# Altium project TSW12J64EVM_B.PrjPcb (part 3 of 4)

## Sheet TSW12J64EVM_B_8_Power.SchDoc
size 431 x 279 mm; Date: Not shown in title block; ApprovedBy: Not shown in title block; CheckedBy: Not shown in title block; Author: Not shown in title block; CompanyName: Not shown in title block; Engineer: Not shown in title block; Organization: Not shown in title block; Address1: Not shown in title block; Address2: Not shown in title block; Address3: Not shown in title block; Address4: Not shown in title block; DocumentNumber: 8; Revision: Use project parameter SCH_Rev; SheetNumber: 8; SheetTotal: 11; PageSetup: Record=PageOptions¦CenterHorizontal=True¦CenterVertical=True¦PrintScale=0.64¦XCorrection=1.00¦YCorrection=1.00¦PrintKind=0¦BorderSize=5000000¦LeftOffset=0¦BottomOffset=0¦Orientation=2¦PaperLength=1000¦PaperWidth=1000¦Scale=100¦PaperSource=15¦PrintQuality=600¦MediaType=1¦DitherType=10¦PaperKind=11x17¦PrintScaleMode=1
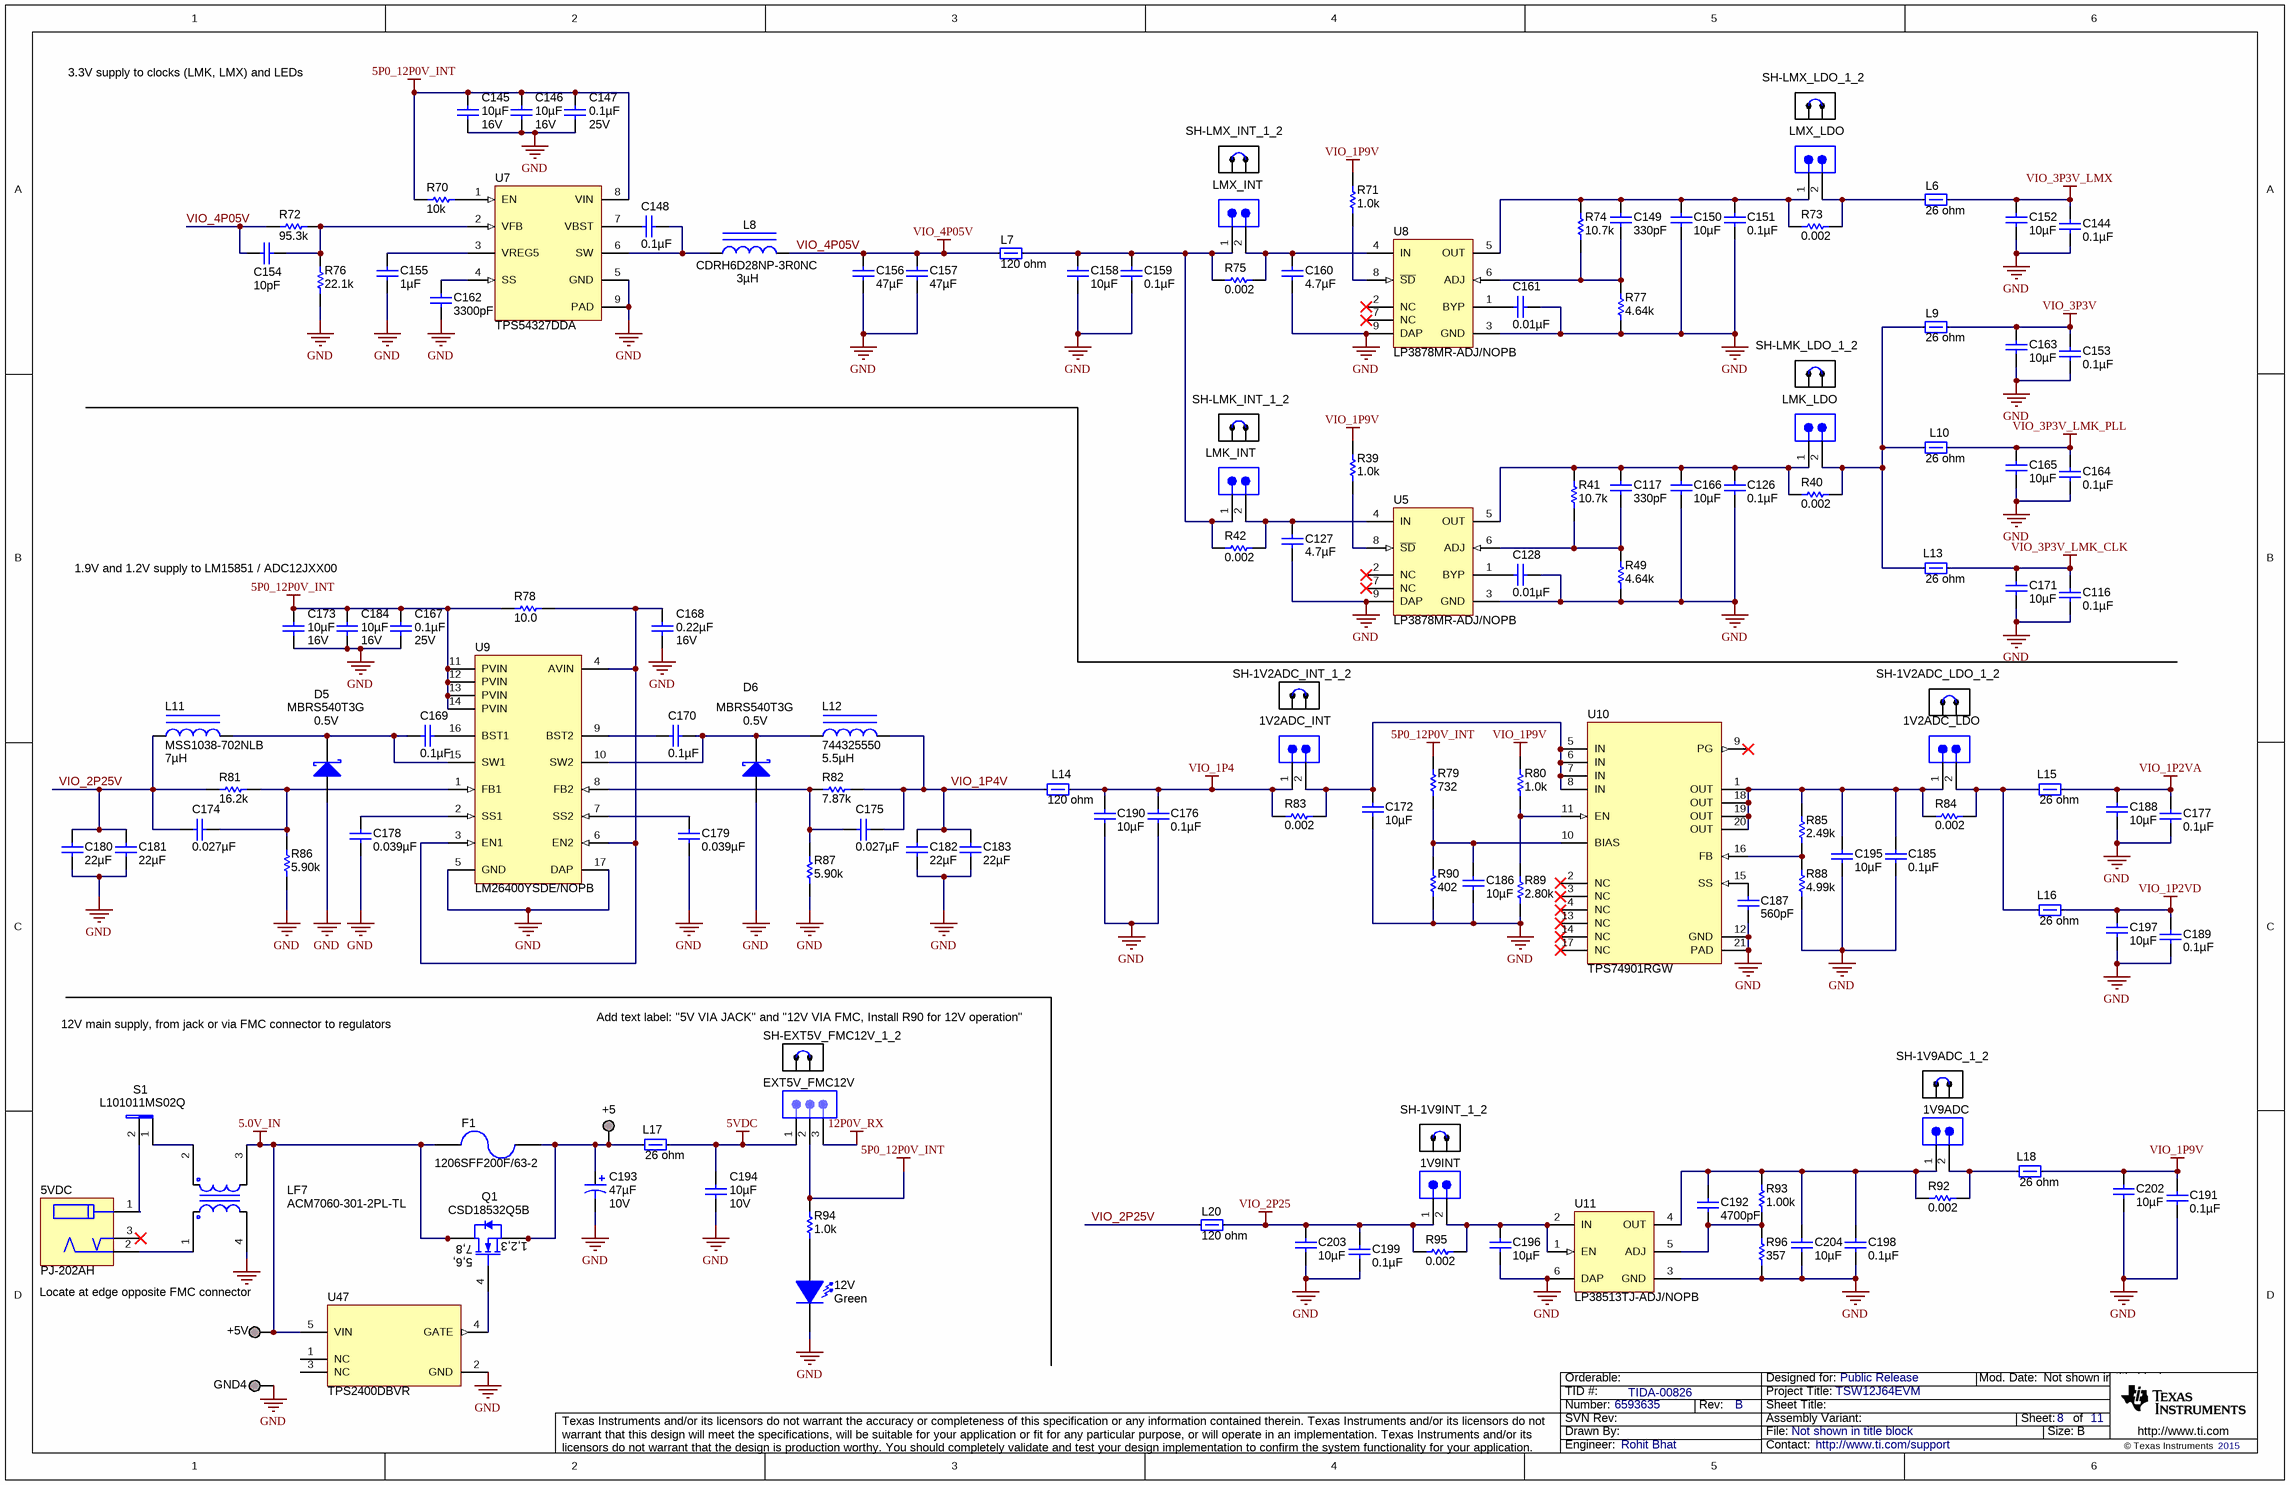
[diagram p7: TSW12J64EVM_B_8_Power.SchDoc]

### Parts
1V2ADC_INT  TSW-102-07-G-S  [TSW-102-07-G-S]  (value not drawn)
1V2ADC_LDO  TSW-102-07-G-S  [TSW-102-07-G-S]  (value not drawn)
1V9ADC  TSW-102-07-G-S  [TSW-102-07-G-S]  (value not drawn)
1V9INT  TSW-102-07-G-S  [TSW-102-07-G-S]  (value not drawn)
5VDC  PJ-202AH  [CONN_CUI-PJ-202AH]
12V  value Green  [LED_LTST-C190]  (hidden comment: LTST-C190GKT)
+5  TESTPOINT  [TP_VIA_060RND040]  (value not drawn)  (no BOM)
+5V  TESTPOINT  [TP_VIA_060RND040]  (value not drawn)  (no BOM)
C116  ValueDisplayed: 0.1µF  [0603L]  (hidden comment: 06033C104JAT2A)
C117  ValueDisplayed: 330pF  [0603L]  (hidden comment: 06035A331JAT2A)
C126  ValueDisplayed: 0.1µF  [0603L]  (hidden comment: 06033C104JAT2A)
C127  ValueDisplayed: 4.7µF  [0603L]  (hidden comment: C0603C475K8PACTU)
C128  ValueDisplayed: 0.01µF  [0603L]  (hidden comment: 06031C103MAT2A)
C144  ValueDisplayed: 0.1µF  [0603L]  (hidden comment: 06033C104JAT2A)
C145  ValueDisplayed: 10µF  Value2: 16V  [0805L]  (hidden comment: EMK212BJ106KG-T)
C146  ValueDisplayed: 10µF  Value2: 16V  [0805L]  (hidden comment: EMK212BJ106KG-T)
C147  ValueDisplayed: 0.1µF  Value2: 25V  [0603L]  (hidden comment: 06033C104JAT2A)
C148  ValueDisplayed: 0.1µF  [0603L]  (hidden comment: 06033C104JAT2A)
C149  ValueDisplayed: 330pF  [0603L]  (hidden comment: 06035A331JAT2A)
C150  ValueDisplayed: 10µF  [0603L]  (hidden comment: C1608X5R1A106M)
C151  ValueDisplayed: 0.1µF  [0603L]  (hidden comment: 06033C104JAT2A)
C152  ValueDisplayed: 10µF  [0603L]  (hidden comment: C1608X5R1A106M)
C153  ValueDisplayed: 0.1µF  [0603L]  (hidden comment: 06033C104JAT2A)
C154  ValueDisplayed: 10pF  [0603L]  (hidden comment: 06035A100JAT2A)
C155  ValueDisplayed: 1µF  [0603L]  (hidden comment: C1608X5R1C105K)
C156  ValueDisplayed: 47µF  [1206L]  (hidden comment: GRM31CR60J476ME19L)
C157  ValueDisplayed: 47µF  [1206L]  (hidden comment: GRM31CR60J476ME19L)
C158  ValueDisplayed: 10µF  [0603L]  (hidden comment: C1608X5R1A106M)
C159  ValueDisplayed: 0.1µF  [0603L]  (hidden comment: 06033C104JAT2A)
C160  ValueDisplayed: 4.7µF  [0603L]  (hidden comment: C0603C475K8PACTU)
C161  ValueDisplayed: 0.01µF  [0603L]  (hidden comment: 06031C103MAT2A)
C162  ValueDisplayed: 3300pF  [0603L]  (hidden comment: GRM188R71E332KA01D)
C163  ValueDisplayed: 10µF  [0603L]  (hidden comment: C1608X5R1A106M)
C164  ValueDisplayed: 0.1µF  [0603L]  (hidden comment: 06033C104JAT2A)
C165  ValueDisplayed: 10µF  [0603L]  (hidden comment: C1608X5R1A106M)
C166  ValueDisplayed: 10µF  [0603L]  (hidden comment: C1608X5R1A106M)
C167  ValueDisplayed: 0.1µF  Value2: 25V  [0603L]  (hidden comment: 06033C104JAT2A)
C168  ValueDisplayed: 0.22µF  Value2: 16V  [0603L]  (hidden comment: C1608X7R1C224K)
C169  ValueDisplayed: 0.1µF  [0402L]  (hidden comment: GRM155R60J104KA01D)
C170  ValueDisplayed: 0.1µF  [0402L]  (hidden comment: GRM155R60J104KA01D)
C171  ValueDisplayed: 10µF  [0603L]  (hidden comment: C1608X5R1A106M)
C172  ValueDisplayed: 10µF  [0603L]  (hidden comment: C1608X5R1A106M)
C173  ValueDisplayed: 10µF  Value2: 16V  [0805L]  (hidden comment: EMK212BJ106KG-T)
C174  ValueDisplayed: 0.027µF  [0603L]  (hidden comment: GRM188R71C273KA01D)
C175  ValueDisplayed: 0.027µF  [0603L]  (hidden comment: GRM188R71C273KA01D)
C176  ValueDisplayed: 0.1µF  [0603L]  (hidden comment: 06033C104JAT2A)
C177  ValueDisplayed: 0.1µF  [0603L]  (hidden comment: 06033C104JAT2A)
C178  ValueDisplayed: 0.039µF  [0603L]  (hidden comment: 06033C393KAT2A)
C179  ValueDisplayed: 0.039µF  [0603L]  (hidden comment: 06033C393KAT2A)
C180  ValueDisplayed: 22µF  [1206L]  (hidden comment: GRM31CR61A226ME19L)
C181  ValueDisplayed: 22µF  [1206L]  (hidden comment: GRM31CR61A226ME19L)
C182  ValueDisplayed: 22µF  [1206L]  (hidden comment: GRM31CR61A226ME19L)
C183  ValueDisplayed: 22µF  [1206L]  (hidden comment: GRM31CR61A226ME19L)
C184  ValueDisplayed: 10µF  Value2: 16V  [0805L]  (hidden comment: EMK212BJ106KG-T)
C185  ValueDisplayed: 0.1µF  [0603L]  (hidden comment: 06033C104JAT2A)
C186  ValueDisplayed: 10µF  [0603L]  (hidden comment: C1608X5R1A106M)
C187  ValueDisplayed: 560pF  [0603L]  (hidden comment: 06035A561JAT2A)
C188  ValueDisplayed: 10µF  [0603L]  (hidden comment: C1608X5R1A106M)
C189  ValueDisplayed: 0.1µF  [0603L]  (hidden comment: 06033C104JAT2A)
C190  ValueDisplayed: 10µF  [0603L]  (hidden comment: C1608X5R1A106M)
C191  ValueDisplayed: 0.1µF  [0603L]  (hidden comment: 06033C104JAT2A)
C192  ValueDisplayed: 4700pF  [0603L]  (hidden comment: GRM188R71C472KA01D)
C193  ValueDisplayed: 47µF  Value2: 10V  [3528-21]  (hidden comment: TPSB476K010R0250)
C194  ValueDisplayed: 10µF  Value2: 10V  [0603L]  (hidden comment: C1608X5R1A106M)
C195  ValueDisplayed: 10µF  [0603L]  (hidden comment: C1608X5R1A106M)
C196  ValueDisplayed: 10µF  [0603L]  (hidden comment: C1608X5R1A106M)
C197  ValueDisplayed: 10µF  [0603L]  (hidden comment: C1608X5R1A106M)
C198  ValueDisplayed: 0.1µF  [0603L]  (hidden comment: 06033C104JAT2A)
C199  ValueDisplayed: 0.1µF  [0603L]  (hidden comment: 06033C104JAT2A)
C202  ValueDisplayed: 10µF  [0603L]  (hidden comment: C1608X5R1A106M)
C203  ValueDisplayed: 10µF  [0603L]  (hidden comment: C1608X5R1A106M)
C204  ValueDisplayed: 10µF  [0603L]  (hidden comment: C1608X5R1A106M)
D5  MBRS540T3G  value 0.5V  [SMC]
D6  MBRS540T3G  value 0.5V  [SMC]
EXT5V_FMC12V  PBC03SAAN  [PBC03SAAN]  (value not drawn)
F1  1206SFF200F/63-2  [1206]
GND4  TESTPOINT  [TP_VIA_060RND040]  (value not drawn)  (no BOM)
L6  value 26 ohm  [0603]  (hidden comment: BLM18SG260TN1D)
L7  value 120 ohm  [0603]  (hidden comment: BLM18SG121TN1D)
L8  CDRH6D28NP-3R0NC  ValueDisplayed: 3µH  [CDRH6D28]
L9  value 26 ohm  [0603]  (hidden comment: BLM18SG260TN1D)
L10  value 26 ohm  [0603]  (hidden comment: BLM18SG260TN1D)
L11  MSS1038-702NLB  ValueDisplayed: 7µH  [MSS1038]
L12  744325550  ValueDisplayed: 5.5µH  [WE-HC6]
L13  value 26 ohm  [0603]  (hidden comment: BLM18SG260TN1D)
L14  value 120 ohm  [0603]  (hidden comment: BLM18SG121TN1D)
L15  value 26 ohm  [0603]  (hidden comment: BLM18SG260TN1D)
L16  value 26 ohm  [0603]  (hidden comment: BLM18SG260TN1D)
L17  value 26 ohm  [0603]  (hidden comment: BLM18SG260TN1D)
L18  value 26 ohm  [0603]  (hidden comment: BLM18SG260TN1D)
L20  value 120 ohm  [0603]  (hidden comment: BLM18SG121TN1D)
LF7  ACM7060-301-2PL-TL  [IND_TDK_ACM7060]
LMK_INT  TSW-102-07-G-S  [TSW-102-07-G-S]  (value not drawn)
LMK_LDO  TSW-102-07-G-S  [TSW-102-07-G-S]  (value not drawn)
LMX_INT  TSW-102-07-G-S  [TSW-102-07-G-S]  (value not drawn)
LMX_LDO  TSW-102-07-G-S  [TSW-102-07-G-S]  (value not drawn)
Q1  CSD18532Q5B  [TRANS_NexFET_Q5B]
R39  value 1.0k  [0603L]  (hidden comment: RC0603JR-071KL)
R40  value 0.002  [1206]  (hidden comment: CSNL1206FT2L00)
R41  value 10.7k  [0603L]  (hidden comment: CRCW060310K7FKEA)
R42  value 0.002  [1206]  (hidden comment: CSNL1206FT2L00)
R49  value 4.64k  [0603L]  (hidden comment: RC0603FR-074K64L)
R70  value 10k  [0603L]  (hidden comment: RC0603JR-0710KL)
R71  value 1.0k  [0603L]  (hidden comment: RC0603JR-071KL)
R72  ValueDisplayed: 95.3k  [0603L]  (hidden comment: RC0603FR-0795K3L)
R73  value 0.002  [1206]  (hidden comment: CSNL1206FT2L00)
R74  value 10.7k  [0603L]  (hidden comment: CRCW060310K7FKEA)
R75  value 0.002  [1206]  (hidden comment: CSNL1206FT2L00)
R76  value 22.1k  [0603L]  (hidden comment: CRCW060322K1FKEA)
R77  value 4.64k  [0603L]  (hidden comment: RC0603FR-074K64L)
R78  value 10.0  [0603L]  (hidden comment: RC0603FR-0710RL)
R79  value 732  [0603L]  (hidden comment: CRCW0603732RFKEA)
R80  value 1.0k  [0603L]  (hidden comment: RC0603JR-071KL)
R81  value 16.2k  [0603L]  (hidden comment: CRCW060316K2FKEA)
R82  value 7.87k  [0603L]  (hidden comment: CRCW06037K87FKEA)
R83  value 0.002  [1206]  (hidden comment: CSNL1206FT2L00)
R84  value 0.002  [1206]  (hidden comment: CSNL1206FT2L00)
R85  value 2.49k  [0603L]  (hidden comment: CRCW06032K49FKEA)
R86  value 5.90k  [0603L]  (hidden comment: CRCW06035K90FKEA)
R87  value 5.90k  [0603L]  (hidden comment: CRCW06035K90FKEA)
R88  value 4.99k  [0603L]  (hidden comment: CRCW06034K99FKEA)
R89  value 2.80k  [0603L]  (hidden comment: CRCW06032K80FKEA)
R90  value 402  [0603L]  (hidden comment: RC0603FR-07402RL)
R92  value 0.002  [1206]  (hidden comment: CSNL1206FT2L00)
R93  value 1.00k  [0603L]  (hidden comment: RC0603FR-071KL)
R94  value 1.0k  [1206L]  (hidden comment: CRCW12061K00JNEA)
R95  value 0.002  [1206]  (hidden comment: CSNL1206FT2L00)
R96  value 357  [0603L]  (hidden comment: RC0603FR-07357RL)
S1  L101011MS02Q  [SW_ L101011MS02Q]
SH-1V2ADC_INT_1_2  SNT-100-BK-G  [SNT-100-BK-G]  (value not drawn)
SH-1V2ADC_LDO_1_2  SNT-100-BK-G  [SNT-100-BK-G]  (value not drawn)
SH-1V9ADC_1_2  SNT-100-BK-G  [SNT-100-BK-G]  (value not drawn)
SH-1V9INT_1_2  SNT-100-BK-G  [SNT-100-BK-G]  (value not drawn)
SH-EXT5V_FMC12V_1_2  SNT-100-BK-G  [SNT-100-BK-G]  (value not drawn)
SH-LMK_INT_1_2  SNT-100-BK-G  [SNT-100-BK-G]  (value not drawn)
SH-LMK_LDO_1_2  SNT-100-BK-G  [SNT-100-BK-G]  (value not drawn)
SH-LMX_INT_1_2  SNT-100-BK-G  [SNT-100-BK-G]  (value not drawn)
SH-LMX_LDO_1_2  SNT-100-BK-G  [SNT-100-BK-G]  (value not drawn)
U5  LP3878MR-ADJ/NOPB  [MRA08A_N]
U7  TPS54327DDA  [DDA0008B_L]
U8  LP3878MR-ADJ/NOPB  [MRA08A_N]
U9  LM26400YSDE/NOPB  [SDA16A]
U10  TPS74901RGW  [RGW0020A]
U11  LP38513TJ-ADJ/NOPB  [TJ5A_N]
U47  TPS2400DBVR  [DBV0005A_N]

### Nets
5.0V_IN: +5V.1 F1.2 LF7.3 Q1.5(D) Q1.6(D) Q1.7(D) Q1.8(D) U47.5(VIN)
5P0_12P0V_INT: C145.1 C146.1 C147.1 C167.1 C173.1 C184.1 EXT5V_FMC12V.2 R70.1 R78.1 R79.2 R94.2 U7.8(VIN) U9.11(PVIN) U9.12(PVIN) U9.13(PVIN) U9.14(PVIN)
5VDC: C194.1 EXT5V_FMC12V.1 L17.2
12P0V_RX: EXT5V_FMC12V.3
GND: 12V.2(K) C116.2 C126.2 C127.2 C128.2 C144.2 C145.2 C146.2 C147.2 C150.2 C151.2 C152.2 C153.2 C155.2 C156.1 C157.1 C158.2 C159.2 C160.2 C161.2 C162.2 C163.2 C164.2 C165.2 C166.2 C167.2 C168.2 C171.2 C172.2 C173.2 C176.2 C177.2 C178.2 C179.2 C180.2 C181.2 C182.2 C183.2 C184.2 C185.2 C186.2 C187.2 C188.2 C189.2 C190.2 C191.2 C193.2(-) C194.2 C195.2 C196.2 C197.2 C198.2 C199.2 C202.2 C203.2 C204.2 D5.2(A) D6.2(A) GND4.1 LF7.4 R49.1 R76.1 R77.1 R86.1 R87.1 R88.1 R89.1 R90.1 R96.1 U5.3(GND) U5.9(DAP) U7.5(GND) U7.9(PAD) U8.3(GND) U8.9(DAP) U9.5(GND) U9.17(DAP) U10.12(GND) U10.21(PAD) U11.3(GND) U11.6(DAP) U47.2(GND)
VIO_1P2VA: C177.1 C188.1 L15.2
VIO_1P2VD: C189.1 C197.1 L16.2
VIO_1P4: 1V2ADC_INT.1 C176.1 C190.1 L14.2 R83.1
VIO_1P9V: C191.1 C202.1 L18.2 R39.1 R71.1 R80.1
VIO_2P25: 1V9INT.1 C199.1 C203.1 L20.2 R95.1
VIO_3P3V: C153.1 C163.1 L9.2
VIO_3P3V_LMK_CLK: C116.1 C171.1 L13.2
VIO_3P3V_LMK_PLL: C164.1 C165.1 L10.2
VIO_3P3V_LMX: C144.1 C152.1 L6.2
VIO_4P05V: C154.2 C156.2 C157.2 L7.1 L8.2 R72.1
VIO_1P4V: C175.1 C182.1 C183.1 L12.2 L14.1 R82.2
VIO_2P25V: C174.2 C180.1 C181.1 L11.1 L20.1 R81.1
Net1V2ADC_INT_2: 1V2ADC_INT.2 C172.1 R83.2 U10.5(IN) U10.6(IN) U10.7(IN) U10.8(IN)
Net1V2ADC_LDO_1: 1V2ADC_LDO.1 C185.1 C195.1 R84.1 R85.2 U10.1(OUT) U10.18(OUT) U10.19(OUT) U10.20(OUT)
Net1V2ADC_LDO_2: 1V2ADC_LDO.2 L15.1 L16.1 R84.2
Net1V9ADC_1: 1V9ADC.1 C192.1 C198.1 C204.1 R92.1 R93.2 U11.4(OUT)
Net1V9ADC_2: 1V9ADC.2 L18.1 R92.2
Net1V9INT_2: 1V9INT.2 C196.1 R95.2 U11.1(EN) U11.2(IN)
Net5VDC_1: 5VDC.1 S1.2
Net5VDC_2: 5VDC.2 LF7.1
Net12V_1: 12V.1(A) R94.1
Net+5_1: +5.1 C193.1(+) F1.1 L17.1 Q1.1(S) Q1.2(S) Q1.3(S)
NetC117_1: C117.1 C126.1 C166.1 LMK_LDO.1 R40.1 R41.2 U5.5(OUT)
NetC117_2: C117.2 R41.1 R49.2 U5.6(ADJ)
NetC127_1: C127.1 LMK_INT.2 R42.2 U5.4(IN)
NetC128_1: C128.1 U5.1(BYP)
NetC148_1: C148.1 L8.1 U7.6(SW)
NetC148_2: C148.2 U7.7(VBST)
NetC149_1: C149.1 C150.1 C151.1 LMX_LDO.1 R73.1 R74.2 U8.5(OUT)
NetC149_2: C149.2 R74.1 R77.2 U8.6(ADJ)
NetC154_1: C154.1 R72.2 R76.2 U7.2(VFB)
NetC155_1: C155.1 U7.3(VREG5)
NetC158_1: C158.1 C159.1 L7.2 LMK_INT.1 LMX_INT.1 R42.1 R75.1
NetC160_1: C160.1 LMX_INT.2 R75.2 U8.4(IN)
NetC161_1: C161.1 U8.1(BYP)
NetC162_1: C162.1 U7.4(SS)
NetC168_1: C168.1 R78.2 U9.3(EN1) U9.4(AVIN) U9.6(EN2)
NetC169_1: C169.1 U9.16(BST1)
NetC169_2: C169.2 D5.1(K) L11.2 U9.15(SW1)
NetC170_1: C170.1 D6.1(K) L12.1 U9.10(SW2)
NetC170_2: C170.2 U9.9(BST2)
NetC174_1: C174.1 R81.2 R86.2 U9.1(FB1)
NetC175_2: C175.2 R82.1 R87.2 U9.8(FB2)
NetC178_1: C178.1 U9.2(SS1)
NetC179_1: C179.1 U9.7(SS2)
NetC186_1: C186.1 R79.1 R90.2 U10.10(BIAS)
NetC187_1: C187.1 U10.15(SS)
NetC192_2: C192.2 R93.1 R96.2 U11.5(ADJ)
NetL6_1: L6.1 LMX_LDO.2 R73.2
NetL9_1: L9.1 L10.1 L13.1 LMK_LDO.2 R40.2
NetLF7_2: LF7.2 S1.1
NetQ1_4: Q1.4(G) U47.4(GATE)
NetR39_2: R39.2 U5.8(~{SD})
NetR70_2: R70.2 U7.1(EN)
NetR71_2: R71.2 U8.8(~{SD})
NetR80_2: R80.2 R89.2 U10.11(EN)
NetR85_1: R85.1 R88.2 U10.16(FB)

Not connected (* = marked no-connect by the designer): 5VDC 3*; U5 2(NC)* 7(NC)*; U8 2(NC)* 7(NC)*; U10 2(NC)* 3(NC)* 4(NC)* 9(PG)* 13(NC)* 14(NC)* 17(NC)*; U47 1(NC) 3(NC)

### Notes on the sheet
- 3.3V supply to clocks (LMK, LMX) and LEDs
- 1.9V and 1.2V supply to LM15851 / ADC12JXX00
- 12V main supply, from jack or via FMC connector to regulators
- (near SH-EXT5V_FMC12V_1_2) Add text label: "5V VIA JACK" and "12V VIA FMC, Install R90 for 12V operation"
- Locate at edge opposite FMC connector

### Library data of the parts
1V2ADC_INT 1V2ADC_LDO 1V9ADC 1V9INT LMK_INT LMK_LDO LMX_INT LMX_LDO = TSW-102-07-G-S: Header, TH, 100mil, 2x1, Gold plated, 230 mil above insulator; Manufacturer: Samtec, Inc.; U/M: EA
5VDC = PJ-202AH: Connector, DC Jack 2.1X5.5 mm, TH; Manufacturer: CUI Inc.; SymbolCreator: a0799628; U/M: EA
12V = LTST-C190GKT: LED, Green, SMD; Manufacturer: Lite-On; Vf_V: 2.1; Value2: 2.1V; Io_A: 0.02; Power_TotalModule: 0.1; Value1: 0.1W; U/M: EA
+5 +5V GND4 = TESTPOINT: TEST POINT.  No entry in BOM.
C116 C126 C144 C147 C148 C151 C153 C159 C164 C167 C176 C177 C185 C189 C191 C198 C199 = 06033C104JAT2A: CAP, CERM, 0.1uF, 25V, +/-5%, X7R, 0603; Manufacturer: AVX; Polarized: N; CompType: Capacitor; U/M: EA; Cap_F: 0.0000001; Tolerance_%: 5; ESR_Ohm: 0.05; Value1: 0.05 ohm; VDC_V: 25; TaMin_C: -55; TaMax_C: 125; Cap_Case: 0603
C117 C149 = 06035A331JAT2A: CAP, CERM, 330pF, 50V, +/-5%, C0G/NP0, 0603; Manufacturer: AVX; Polarized: N; CompType: Capacitor; U/M: EA; Cap_F: 0.00000000033; Tolerance_%: 5; ESR_Ohm: 0.071; Value1: 0.071 ohm; VDC_V: 50; TaMin_C: -55; TaMax_C: 125; Cap_Case: 0603
C127 C160 = C0603C475K8PACTU: CAP, CERM, 4.7uF, 10V, +/-10%, X5R, 0603; Manufacturer: Kemet; Polarized: N; CompType: Capacitor; U/M: EA; Cap_F: 0.0000047; Tolerance_%: 10; ESR_Ohm: 0.006; Value1: 0.006 ohm; IRMS_A: 7.24; TaMin_C: -55; TaMax_C: 85; Cap_Case: 0603
C128 C161 = 06031C103MAT2A: CAP, CERM, 0.01uF, 100V, +/-20%, X7R, 0603; Manufacturer: AVX; Polarized: N; CompType: Capacitor; U/M: EA; Cap_F: 0.00000001; Tolerance_%: 20; ESR_Ohm: 0.098; Value1: 0.098 ohm; VDC_V: 100; TaMin_C: -55; TaMax_C: 125; Cap_Case: 0603
C145 C146 C173 C184 = EMK212BJ106KG-T: CAP, CERM, 10uF, 16V, +/-10%, X5R, 0805; Manufacturer: Taiyo Yuden; Polarized: N; CompType: Capacitor; U/M: EA; Cap_F: 0.00001; Tolerance_%: 10; Value1: Unknown; VDC_V: 16; TaMin_C: -55; TaMax_C: 85; Cap_Case: 0805
C150 C152 C158 C163 C165 C166 C171 C172 C186 C188 C190 C194-C197 C202-C204 = C1608X5R1A106M: CAP, CERM, 10uF, 10V, +/-10%, C0G/NP0, 0603; Manufacturer: TDK; Polarized: N; CompType: Capacitor; U/M: EA; Cap_F: 0.00001; Tolerance_%: 10; ESR_Ohm: 0.0078; Value1: 0.0078 ohm; IRMS_A: 1.85; TaMin_C: -55; TaMax_C: 85; Cap_Case: 0603
C154 = 06035A100JAT2A: CAP, CERM, 10pF, 50V, +/-5%, C0G/NP0, 0603; Manufacturer: AVX; Polarized: N; CompType: Capacitor; U/M: EA; Cap_F: 0.00000000001; Tolerance_%: 5; ESR_Ohm: 0.403; Value1: 0.403 ohm; VDC_V: 50; TaMin_C: -55; TaMax_C: 125; Cap_Case: 0603
C155 = C1608X5R1C105K: CAP, CERM, 1uF, 16V, +/-10%, X5R, 0603; Manufacturer: TDK; Polarized: N; CompType: Capacitor; U/M: EA; Cap_F: 0.000001; Tolerance_%: 10; ESR_Ohm: 0.0057; Value1: 0.0057 ohm; VDC_V: 16; TaMin_C: -55; TaMax_C: 85; Cap_Case: 0603
C156 C157 = GRM31CR60J476ME19L: CAP, CERM, 47uF, 6.3V, +/-20%, X5R, 1206; Manufacturer: MuRata; Polarized: N; CompType: Capacitor; U/M: EA; Cap_F: 0.000047; Tolerance_%: 20; ESR_Ohm: 0.003; Value1: 0.003 ohm; VDC_V: 6.3; TaMin_C: -55; TaMax_C: 85; Cap_Case: 1206
C162 = GRM188R71E332KA01D: CAP, CERM, 3300pF, 25V, +/-10%, X7R, 0603; Manufacturer: MuRata; Polarized: N; CompType: Capacitor; U/M: EA; Cap_F: 0.0000000033; Tolerance_%: 10; VDC_V: 25; TaMin_C: -55; TaMax_C: 125; Cap_Case: 0603
C168 = C1608X7R1C224K: CAP, CERM, 0.22uF, 16V, +/-10%, X7R, 0603; Manufacturer: TDK; Polarized: N; CompType: Capacitor; U/M: EA; Cap_F: 0.00000022; Tolerance_%: 10; ESR_Ohm: 0.0125; Value1: 0.0125 ohm; VDC_V: 16; TaMin_C: -55; TaMax_C: 125; Cap_Case: 0603
C169 C170 = GRM155R60J104KA01D: CAP, CERM, 0.1uF, 6.3V, +/-10%, X5R, 0402; Manufacturer: MuRata; Polarized: N; CompType: Capacitor; U/M: EA; Cap_F: 0.0000001; Tolerance_%: 10; VDC_V: 6.3; TaMin_C: -55; TaMax_C: 85; Cap_Case: 0402
C174 C175 = GRM188R71C273KA01D: CAP, CERM, 0.027uF, 16V, +/-10%, X7R, 0603; Manufacturer: MuRata; Polarized: N; CompType: Capacitor; U/M: EA; Cap_F: 0.000000027; Tolerance_%: 10; VDC_V: 16; TaMin_C: -55; TaMax_C: 125; Cap_Case: 0603
C178 C179 = 06033C393KAT2A: CAP, CERM, 0.039uF, 25V, +/-10%, X7R, 0603; Manufacturer: AVX; Polarized: N; CompType: Capacitor; U/M: EA; Cap_F: 0.000000039; Tolerance_%: 10; ESR_Ohm: 0.056; Value1: 0.056 ohm; VDC_V: 25; TaMin_C: -55; TaMax_C: 125; Cap_Case: 0603
C180-C183 = GRM31CR61A226ME19L: CAP, CERM, 22uF, 10V, +/-20%, X5R, 1206; Manufacturer: MuRata; Polarized: N; CompType: Capacitor; U/M: EA; Cap_F: 0.000022; Tolerance_%: 20; ESR_Ohm: 0.007; Value1: 0.007 ohm; VDC_V: 10; TaMin_C: -55; TaMax_C: 85; Cap_Case: 1206
C187 = 06035A561JAT2A: CAP, CERM, 560pF, 50V, +/-5%, C0G/NP0, 0603; Manufacturer: AVX; Polarized: N; CompType: Capacitor; U/M: EA; Cap_F: 0.00000000056; Tolerance_%: 5; ESR_Ohm: 0.059; Value1: 0.059 ohm; VDC_V: 50; TaMin_C: -55; TaMax_C: 125; Cap_Case: 0603
C192 = GRM188R71C472KA01D: CAP, CERM, 4700pF, 16V, +/-10%, X7R, 0603; Manufacturer: MuRata; Polarized: N; CompType: Capacitor; U/M: EA; Cap_F: 0.0000000047; Tolerance_%: 10; VDC_V: 16; TaMin_C: -55; TaMax_C: 125; Cap_Case: 0603
C193 = TPSB476K010R0250: CAP, TA, 47 µF, 10 V, +/- 10%, 0.25 ohm, SMD; Manufacturer: AVX; Polarized: Y; CompType: Capacitor; Value: 47uF; U/M: EA; Cap_F: 0.000047; Tolerance_%: 10; ESR_ohm: 0.25; IRMS_A: 0.525; TaMin_C: -55; TaMax_C: 125; Cap_Case: B; AEC Category: Q200
D5 D6 = MBRS540T3G: Diode, Schottky, 40V, 5A, SMC; Manufacturer: ON Semiconductor; U/M: EA; Vf_V: 0.5; Io_A: 5; Vr_V: 40; TJmax_C: 150; RJC_CperW: 12
EXT5V_FMC12V = PBC03SAAN: Header, TH, 100mil, 1x3, Gold plated, 230 mil above insulator; Manufacturer: Sullins Connector Solutions; U/M: EA
F1 = 1206SFF200F/63-2: Fuse, 2 A, 63 V, SMD; Manufacturer: TE Connectivity; U/M: EA; VDC_V: 63; Interrupt_DC: 50; Irating_A: 2; Rtyp_Ohm: 0.05; MeltingTyp: 0.07
L6 L9 L10 L13 L15-L18 = BLM18SG260TN1D: 6A Ferrite Bead, 26 ohm @ 100MHz, SMD; Manufacturer: MuRata; Imax_A: 6; DCR_ohm: 0.007; Value1: 0.007 ohm; ZTyp@100MHz_Ohm: 26; U/M: EA
L7 L14 L20 = BLM18SG121TN1D: 3A Ferrite Bead, 120 ohm @ 100MHz, SMD; Manufacturer: MuRata; Imax_A: 3; DCR_ohm: 0.025; Value1: 0.025 ohm; ZTyp@100MHz_Ohm: 120; U/M: EA
L8 = CDRH6D28NP-3R0NC: Inductor, Shielded Drum Core, Ferrite, 3uH, 3A, 0.024 ohm, SMD; Manufacturer: Sumida; Ind_H: 3.0E-6; Imax_A: 3; Irms: 3A @ 30C rise; Isat: 3A @ 35% inductance drop; DCR_ohm: 0.024; U/M: EA
L11 = MSS1038-702NLB: Inductor, Shielded Drum Core, Ferrite, 7uH, 4.35A, 0.03 ohm, SMD; Manufacturer: Coilcraft; Ind_H: 7.0E-6; Imax_A: 4.35; Irms: 4.35A @ 40C rise; Isat: 5.6A @ 30% inductance drop; DCR_ohm: 0.03; U/M: EA
L12 = 744325550: Inductor, Shielded Drum Core, Superflux, 5.5uH, 10A, 0.0112 ohm, SMD; Manufacturer: Wurth Elektronik eiSos; Ind_H: 5.5E-6; Imax_A: 10; Irms: 10A @ 50C rise; Isat: 12A @ 30% inductance drop; DCR_ohm: 0.0112; U/M: EA
LF7 = ACM7060-301-2PL-TL: Coupled inductor, 5A, 0.01 ohm, SMD; Manufacturer: TDK; SymbolCreator: a0799628; Config: Common Chokes; Value: uH; DCR_Ohm: 0.01; Isat: 5; U/M: EA
Q1 = CSD18532Q5B: MOSFET, N-CH, 60 V, 172 A, SON 5x6mm; Manufacturer: Texas Instruments; Alternate Manufacturer: None; U/M: EA; ChType: N; Value: 60V; VdsMax_V: 60; Value1: 3.3 ohm; Rdson45_ohm: 3.3; Value2: 27 nC; QgTyp_nC: 27; Vgs_V: 1.6; IdsMax_A: 172; AEC Category: Q101
R39 R71 R80 = RC0603JR-071KL: RES, 1.0k ohm, 5%, 0.1W, 0603; Manufacturer: Yageo America; CompType: Resistor; Res_ohm: 1000; Value_Code: 1k00; Tolerance_%: 5; Power_W: 0.1; VDC_V: 50; TempCo: 100 ppm/C; EIA_Code: E24; U/M: EA
R40 R42 R73 R75 R83 R84 R92 R95 = CSNL1206FT2L00: RES, 0.002 ohm, 1%, 1W, 1206; Manufacturer: Stackpole Electronics Inc; CompType: Resistor; Value_Code: R002; Tolerance_%: 1; TempCo: 50 ppm/C; U/M: EA
R41 R74 = CRCW060310K7FKEA: RES, 10.7k ohm, 1%, 0.1W, 0603; Manufacturer: Vishay-Dale; CompType: Resistor; Res_ohm: 10700; Value_Code: 10k7; Tolerance_%: 1; Power_W: 0.1; VDC_V: 75; TempCo: 100 ppm/C; EIA_Code: E96; U/M: EA
R49 R77 = RC0603FR-074K64L: RES, 4.64k ohm, 1%, 0.1W, 0603; Manufacturer: Yageo America; CompType: Resistor; Res_ohm: 4640; Value_Code: 4k64; Tolerance_%: 1; Power_W: 0.1; VDC_V: 150; TempCo: 200 ppm/C; EIA_Code: E96; U/M: EA
R70 = RC0603JR-0710KL: RES, 10k ohm, 5%, 0.1W, 0603; Manufacturer: Yageo America; CompType: Resistor; Res_ohm: 10000; Value_Code: 10k0; Tolerance_%: 5; Power_W: 0.1; VDC_V: 50; TempCo: 100 ppm/C; EIA_Code: E24; U/M: EA
R72 = RC0603FR-0795K3L: RES, 95.3 k, 1%, 0.1 W, 0603; Manufacturer: Yageo America; CompType: Resistor; Value: 95.3k; Res_ohm: 95300; Value_Code: 95k3; Tolerance_%: 1; Power_W: 0.1; Value2: 0.1W; VDC_V: 150; TempCo: 200 ppm/C; EIA_Code: E96; U/M: EA
R76 = CRCW060322K1FKEA: RES, 22.1k ohm, 1%, 0.1W, 0603; Manufacturer: Vishay-Dale; CompType: Resistor; Res_ohm: 22100; Value_Code: 22k1; Tolerance_%: 1; Power_W: 0.1; VDC_V: 75; TempCo: 100 ppm/C; EIA_Code: E96; U/M: EA
R78 = RC0603FR-0710RL: RES, 10.0 ohm, 1%, 0.1W, 0603; Manufacturer: Yageo America; CompType: Resistor; Res_ohm: 10; Value_Code: 10R0; Tolerance_%: 1; Power_W: 0.1; VDC_V: 150; TempCo: 200 ppm/C; EIA_Code: E96; U/M: EA
R79 = CRCW0603732RFKEA: RES, 732 ohm, 1%, 0.1W, 0603; Manufacturer: Vishay-Dale; CompType: Resistor; Value_Code: 732R; Tolerance_%: 1; Power_W: 0.1; VDC_V: 75; TempCo: 100 ppm/C; EIA_Code: E96; U/M: EA
R81 = CRCW060316K2FKEA: RES, 16.2k ohm, 1%, 0.1W, 0603; Manufacturer: Vishay-Dale; CompType: Resistor; Res_ohm: 16200; Value_Code: 16k2; Tolerance_%: 1; Power_W: 0.1; VDC_V: 75; TempCo: 100 ppm/C; EIA_Code: E96; U/M: EA
R82 = CRCW06037K87FKEA: RES, 7.87k ohm, 1%, 0.1W, 0603; Manufacturer: Vishay-Dale; CompType: Resistor; Res_ohm: 7870; Value_Code: 7k87; Tolerance_%: 1; Power_W: 0.1; VDC_V: 75; TempCo: 100 ppm/C; EIA_Code: E96; U/M: EA
R85 = CRCW06032K49FKEA: RES, 2.49k ohm, 1%, 0.1W, 0603; Manufacturer: Vishay-Dale; CompType: Resistor; Res_ohm: 2490; Value_Code: 2k49; Tolerance_%: 1; Power_W: 0.1; VDC_V: 75; TempCo: 100 ppm/C; EIA_Code: E96; U/M: EA
R86 R87 = CRCW06035K90FKEA: RES, 5.90k ohm, 1%, 0.1W, 0603; Manufacturer: Vishay-Dale; CompType: Resistor; Res_ohm: 5900; Value_Code: 5k90; Tolerance_%: 1; Power_W: 0.1; VDC_V: 75; TempCo: 100 ppm/C; EIA_Code: E96; U/M: EA
R88 = CRCW06034K99FKEA: RES, 4.99k ohm, 1%, 0.1W, 0603; Manufacturer: Vishay-Dale; CompType: Resistor; Res_ohm: 4990; Value_Code: 4k99; Tolerance_%: 1; Power_W: 0.1; VDC_V: 75; TempCo: 100 ppm/C; EIA_Code: E96; U/M: EA
R89 = CRCW06032K80FKEA: RES, 2.80k ohm, 1%, 0.1W, 0603; Manufacturer: Vishay-Dale; CompType: Resistor; Res_ohm: 2800; Value_Code: 2k80; Tolerance_%: 1; Power_W: 0.1; VDC_V: 75; TempCo: 100 ppm/C; EIA_Code: E96; U/M: EA
R90 = RC0603FR-07402RL: RES, 402 ohm, 1%, 0.1W, 0603; Manufacturer: Yageo America; CompType: Resistor; Value_Code: 402R; Tolerance_%: 1; Power_W: 0.1; VDC_V: 150; TempCo: 200 ppm/C; EIA_Code: E96; U/M: EA
R93 = RC0603FR-071KL: RES, 1.00k ohm, 1%, 0.1W, 0603; Manufacturer: Yageo America; CompType: Resistor; Res_ohm: 1000; Value_Code: 1k00; Tolerance_%: 1; Power_W: 0.1; VDC_V: 150; TempCo: 200 ppm/C; EIA_Code: E96; U/M: EA
R94 = CRCW12061K00JNEA: RES, 1.0k ohm, 5%, 0.25W, 1206; Manufacturer: Vishay-Dale; CompType: Resistor; Res_ohm: 1000; Value_Code: 1k00; Tolerance_%: 5; Power_W: 0.25; VDC_V: 200; TempCo: 200 ppm/C; EIA_Code: E24; U/M: EA
R96 = RC0603FR-07357RL: RES, 357 ohm, 1%, 0.1W, 0603; Manufacturer: Yageo America; CompType: Resistor; Value_Code: 357R; Tolerance_%: 1; Power_W: 0.1; VDC_V: 150; TempCo: 200 ppm/C; EIA_Code: E96; U/M: EA
S1 = L101011MS02Q: SWITCH SLIDE SPST 4A PCB, TH; Manufacturer: C&K Components; Symbol Creator: a0411947; VDC_V: 125; SwitchFunction: Off-On; PositionCount: 1; CurrentRating_mA: 4000
SH-1V2ADC_INT_1_2 SH-1V2ADC_LDO_1_2 SH-1V9ADC_1_2 SH-1V9INT_1_2 SH-EXT5V_FMC12V_1_2 SH-LMK_INT_1_2 SH-LMK_LDO_1_2 SH-LMX_INT_1_2 SH-LMX_LDO_1_2 = SNT-100-BK-G: Shunt, 100mil, Gold plated, Black; Manufacturer: Samtec, Inc.; Alternate Manufacturer: 3M; Alternate PartNumber: 969102-0000-DA; Value: 1x2; Note: You can "mate" this to a header by matching the designator.  i.e. use SH-J3 for header J3
U5 U8 = LP3878MR-ADJ/NOPB: Micropower 800mA Low Noise "Ceramic Stable" Adjustable Voltage Regulator for 1V to 5V Applications, 8-pin PSOP, Pb-Free; Manufacturer: Texas Instruments; PackageTopMarking: NSXYTT*3878*MRADJ; PowerWise: N; CompType: LDO IC
U7 = TPS54327DDA: 3-A OUTPUT SINGLE SYNCRONOUS STEP DOWN SWITCHER WITH INTEGRATED FET(SWIFT), DDA0008B; Alternate Manufacturer: None; Manufacturer: Texas Instruments; SymbolCreator: a0411947; CompType: IC; U/M: EA
U9 = LM26400YSDE/NOPB: Dual 2A, 500kHz Wide Input Range Buck Regulator, 16-pin LLP, Pb-Free; Manufacturer: Texas Instruments; PackageTopMarking: NS*UZXYTT*L26400Y; PowerWise: N; CompType: Switcher
U10 = TPS74901RGW: 3.0A Low Dropout Linear Regulator with Programmable Soft-Start, RGW0020A; Alternate Manufacturer: None; Manufacturer: Texas Instruments; SymbolCreator: a0411947; CompType: IC; U/M: EA
U11 = LP38513TJ-ADJ/NOPB: 3A Fast-Transient Response Adjustable Low-Dropout Linear Voltage Regulator, 5-pin TO-263 Thin, Pb-Free; Manufacturer: Texas Instruments; PackageTopMarking: NSUZXYTTE#*LP38513*TJ-ADJ; PowerWise: N; CompType: LDO IC
U47 = TPS2400DBVR: OVERVOLTAGE PROTECTION CONTROLLER, DBV0005A; Alternate PartNumber: TPS2400DBVT; Manufacturer: Texas Instruments; SymbolCreator: Altium; CompType: IC; U/M: EA

## Sheet TSW12J64EVM_B_9_Power.SchDoc
size 431 x 279 mm; Date: Not shown in title block; ApprovedBy: Not shown in title block; CheckedBy: Not shown in title block; Author: Not shown in title block; CompanyName: Not shown in title block; Engineer: Not shown in title block; Organization: Not shown in title block; Address1: Not shown in title block; Address2: Not shown in title block; Address3: Not shown in title block; Address4: Not shown in title block; DocumentNumber: 9; Revision: Use project parameter SCH_Rev; SheetNumber: 9; SheetTotal: 11; PageSetup: Record=PageOptions¦CenterHorizontal=True¦CenterVertical=True¦PrintScale=1.00¦XCorrection=1.00¦YCorrection=1.00¦PrintKind=0¦BorderSize=5000000¦LeftOffset=0¦BottomOffset=0¦Orientation=2¦PaperLength=1000¦PaperWidth=1000¦Scale=100¦PaperSource=15¦PrintQuality=600¦MediaType=1¦DitherType=10¦PaperKind=Letter¦PrintScaleMode=1
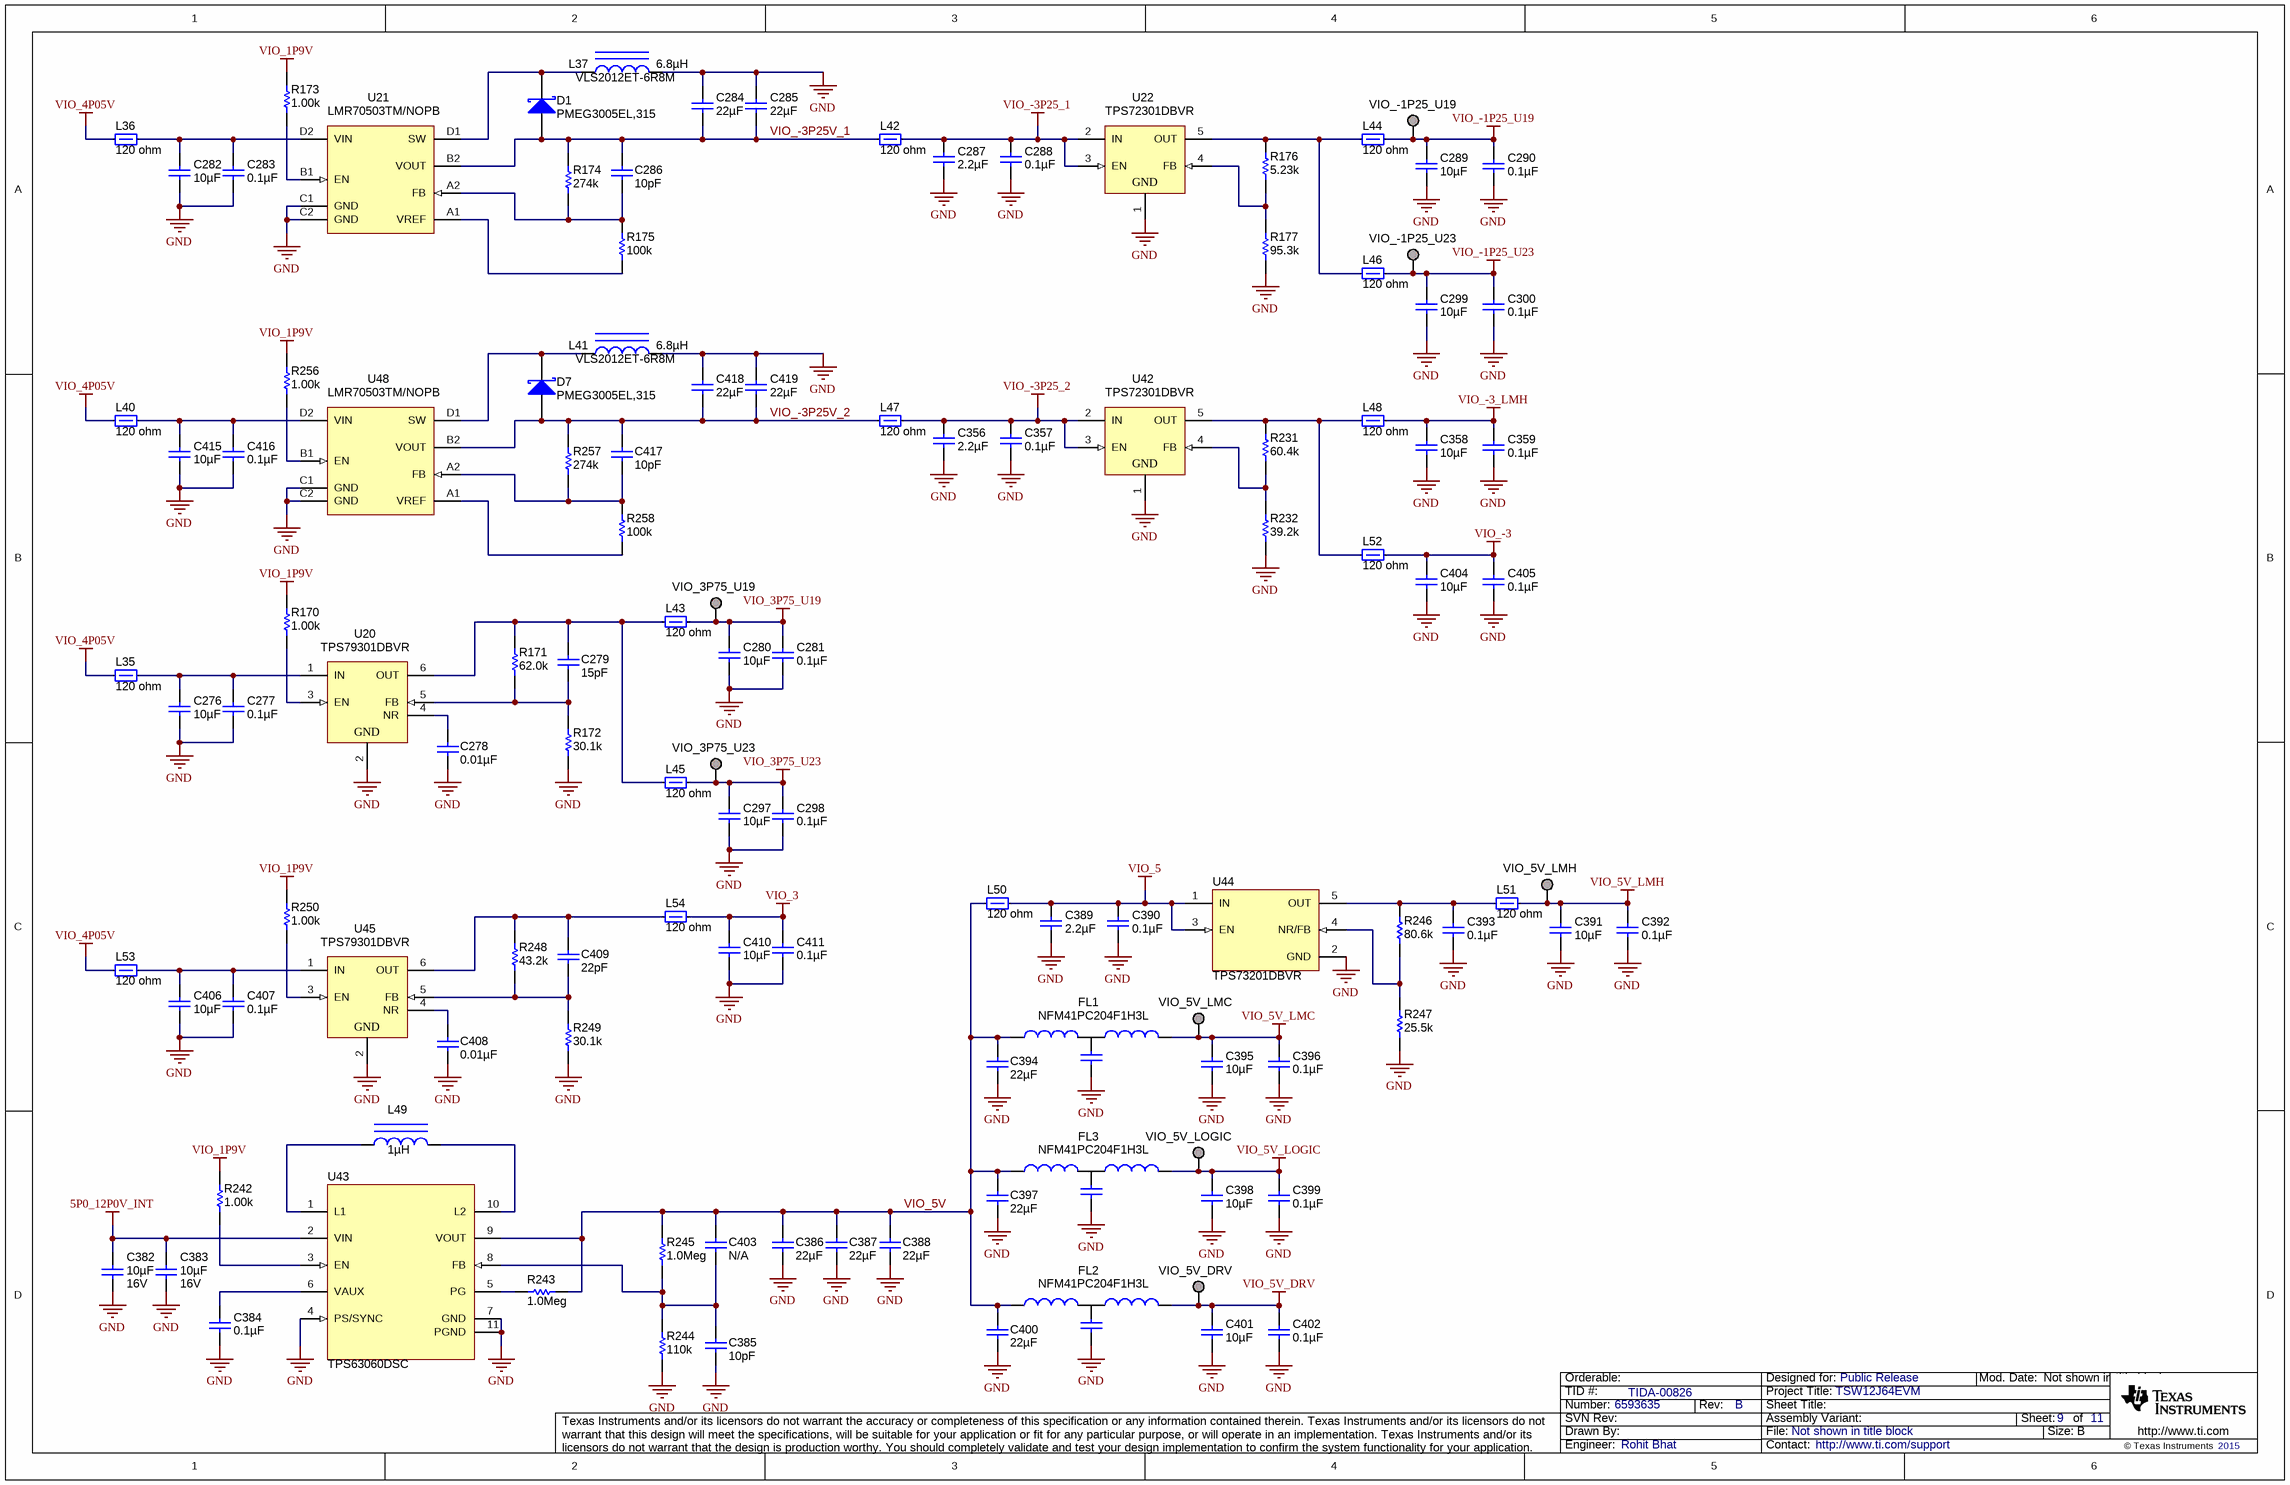
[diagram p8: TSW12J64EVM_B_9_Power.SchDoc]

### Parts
C276  ValueDisplayed: 10µF  [0603L]  (hidden comment: C1608X5R1A106M)
C277  ValueDisplayed: 0.1µF  [0603L]  (hidden comment: 06033C104JAT2A)
C278  ValueDisplayed: 0.01µF  [0603L]  (hidden comment: 06031C103MAT2A)
C279  ValueDisplayed: 15pF  [0603L]  (hidden comment: C0603C150J5GACTU)
C280  ValueDisplayed: 10µF  [0603L]  (hidden comment: C1608X5R1A106M)
C281  ValueDisplayed: 0.1µF  [0603L]  (hidden comment: 06033C104JAT2A)
C282  ValueDisplayed: 10µF  [0603L]  (hidden comment: C1608X5R1A106M)
C283  ValueDisplayed: 0.1µF  [0603L]  (hidden comment: 06033C104JAT2A)
C284  ValueDisplayed: 22µF  [0603L]  (hidden comment: C1608X5R0J226M080AC)
C285  ValueDisplayed: 22µF  [0603L]  (hidden comment: C1608X5R0J226M080AC)
C286  ValueDisplayed: 10pF  [0402L]  (hidden comment: GRM1555C1H100JA01D)
C287  ValueDisplayed: 2.2µF  [0603L]  (hidden comment: GRM188R61A225KE34D)
C288  ValueDisplayed: 0.1µF  [0603L]  (hidden comment: 06033C104JAT2A)
C289  ValueDisplayed: 10µF  [0603L]  (hidden comment: C1608X5R1A106M)
C290  ValueDisplayed: 0.1µF  [0603L]  (hidden comment: 06033C104JAT2A)
C297  ValueDisplayed: 10µF  [0603L]  (hidden comment: C1608X5R1A106M)
C298  ValueDisplayed: 0.1µF  [0603L]  (hidden comment: 06033C104JAT2A)
C299  ValueDisplayed: 10µF  [0603L]  (hidden comment: C1608X5R1A106M)
C300  ValueDisplayed: 0.1µF  [0603L]  (hidden comment: 06033C104JAT2A)
C356  ValueDisplayed: 2.2µF  [0603L]  (hidden comment: GRM188R61A225KE34D)
C357  ValueDisplayed: 0.1µF  [0603L]  (hidden comment: 06033C104JAT2A)
C358  ValueDisplayed: 10µF  [0603L]  (hidden comment: C1608X5R1A106M)
C359  ValueDisplayed: 0.1µF  [0603L]  (hidden comment: 06033C104JAT2A)
C382  ValueDisplayed: 10µF  Value2: 16V  [0805L]  (hidden comment: EMK212BJ106KG-T)
C383  ValueDisplayed: 10µF  Value2: 16V  [0805L]  (hidden comment: EMK212BJ106KG-T)
C384  ValueDisplayed: 0.1µF  [0402L]  (hidden comment: C1005X5R1A104K)
C385  ValueDisplayed: 10pF  [0402L]  (hidden comment: GRM1555C1H100JA01D)
C386  ValueDisplayed: 22µF  [0805L]  (hidden comment: C2012X5R1C226K125AC)
C387  ValueDisplayed: 22µF  [0805L]  (hidden comment: C2012X5R1C226K125AC)
C388  ValueDisplayed: 22µF  [0805L]  (hidden comment: C2012X5R1C226K125AC)
C389  ValueDisplayed: 2.2µF  [0603L]  (hidden comment: GRM188R61A225KE34D)
C390  ValueDisplayed: 0.1µF  [0603L]  (hidden comment: 06033C104JAT2A)
C391  ValueDisplayed: 10µF  [0603L]  (hidden comment: C1608X5R1A106M)
C392  ValueDisplayed: 0.1µF  [0603L]  (hidden comment: 06033C104JAT2A)
C393  ValueDisplayed: 0.1µF  [0603L]  (hidden comment: 06033C104JAT2A)
C394  ValueDisplayed: 22µF  [0805L]  (hidden comment: C2012X5R1C226K125AC)
C395  ValueDisplayed: 10µF  [0603L]  (hidden comment: C1608X5R1A106M)
C396  ValueDisplayed: 0.1µF  [0603L]  (hidden comment: 06033C104JAT2A)
C397  ValueDisplayed: 22µF  [0805L]  (hidden comment: C2012X5R1C226K125AC)
C398  ValueDisplayed: 10µF  [0603L]  (hidden comment: C1608X5R1A106M)
C399  ValueDisplayed: 0.1µF  [0603L]  (hidden comment: 06033C104JAT2A)
C400  ValueDisplayed: 22µF  [0805L]  (hidden comment: C2012X5R1C226K125AC)
C401  ValueDisplayed: 10µF  [0603L]  (hidden comment: C1608X5R1A106M)
C402  ValueDisplayed: 0.1µF  [0603L]  (hidden comment: 06033C104JAT2A)
C403  Used in BOM report  [0402L]  (value not drawn)
C404  ValueDisplayed: 10µF  [0603L]  (hidden comment: C1608X5R1A106M)
C405  ValueDisplayed: 0.1µF  [0603L]  (hidden comment: 06033C104JAT2A)
C406  ValueDisplayed: 10µF  [0603L]  (hidden comment: C1608X5R1A106M)
C407  ValueDisplayed: 0.1µF  [0603L]  (hidden comment: 06033C104JAT2A)
C408  ValueDisplayed: 0.01µF  [0603L]  (hidden comment: 06031C103MAT2A)
C409  ValueDisplayed: 22pF  [0603L]  (hidden comment: C0603C220J5GACTU)
C410  ValueDisplayed: 10µF  [0603L]  (hidden comment: C1608X5R1A106M)
C411  ValueDisplayed: 0.1µF  [0603L]  (hidden comment: 06033C104JAT2A)
C415  ValueDisplayed: 10µF  [0603L]  (hidden comment: C1608X5R1A106M)
C416  ValueDisplayed: 0.1µF  [0603L]  (hidden comment: 06033C104JAT2A)
C417  ValueDisplayed: 10pF  [0402L]  (hidden comment: GRM1555C1H100JA01D)
C418  ValueDisplayed: 22µF  [0603L]  (hidden comment: C1608X5R0J226M080AC)
C419  ValueDisplayed: 22µF  [0603L]  (hidden comment: C1608X5R0J226M080AC)
D1  PMEG3005EL,315  [SOD882]
D7  PMEG3005EL,315  [SOD882]
FL1  NFM41PC204F1H3L  [FIL_NFM41P]
FL2  NFM41PC204F1H3L  [FIL_NFM41P]
FL3  NFM41PC204F1H3L  [FIL_NFM41P]
L35  value 120 ohm  [0603]  (hidden comment: BLM18SG121TN1D)
L36  value 120 ohm  [0603]  (hidden comment: BLM18SG121TN1D)
L37  VLS2012ET-6R8M  ValueDisplayed: 6.8µH  [VLS2012]
L40  value 120 ohm  [0603]  (hidden comment: BLM18SG121TN1D)
L41  VLS2012ET-6R8M  ValueDisplayed: 6.8µH  [VLS2012]
L42  value 120 ohm  [0603]  (hidden comment: BLM18SG121TN1D)
L43  value 120 ohm  [0603]  (hidden comment: BLM18SG121TN1D)
L44  value 120 ohm  [0603]  (hidden comment: BLM18SG121TN1D)
L45  value 120 ohm  [0603]  (hidden comment: BLM18SG121TN1D)
L46  value 120 ohm  [0603]  (hidden comment: BLM18SG121TN1D)
L47  value 120 ohm  [0603]  (hidden comment: BLM18SG121TN1D)
L48  value 120 ohm  [0603]  (hidden comment: BLM18SG121TN1D)
L49  ValueDisplayed: 1µH  [XFL4020]  (hidden comment: XFL4020-102MEB)
L50  value 120 ohm  [0603]  (hidden comment: BLM18SG121TN1D)
L51  value 120 ohm  [0603]  (hidden comment: BLM18SG121TN1D)
L52  value 120 ohm  [0603]  (hidden comment: BLM18SG121TN1D)
L53  value 120 ohm  [0603]  (hidden comment: BLM18SG121TN1D)
L54  value 120 ohm  [0603]  (hidden comment: BLM18SG121TN1D)
R170  value 1.00k  [0402L]  (hidden comment: CRCW04021K00FKED)
R171  ValueDisplayed: 62.0k  [0603L]  (hidden comment: RC0603FR-0762KL)
R172  ValueDisplayed: 30.1k  [0603L]  (hidden comment: CRCW060330K1FKEA)
R173  value 1.00k  [0402L]  (hidden comment: CRCW04021K00FKED)
R174  ValueDisplayed: 274k  [0402L]  (hidden comment: CRCW0402274KFKED)
R175  ValueDisplayed: 100k  [0402L]  (hidden comment: CRCW0402100KFKED)
R176  ValueDisplayed: 5.23k  [0603L]  (hidden comment: CRCW06035K23FKEA)
R177  ValueDisplayed: 95.3k  [0603L]  (hidden comment: RC0603FR-0795K3L)
R231  ValueDisplayed: 60.4k  [0603L]  (hidden comment: CRCW060360K4FKEA)
R232  ValueDisplayed: 39.2k  [0603L]  (hidden comment: RC0603FR-0739K2L)
R242  value 1.00k  [0402L]  (hidden comment: CRCW04021K00FKED)
R243  value 1.0Meg  [0402L]  (hidden comment: CRCW04021M00JNED)
R244  ValueDisplayed: 110k  [0402L]  (hidden comment: CRCW0402110KFKED)
R245  value 1.0Meg  [0402L]  (hidden comment: CRCW04021M00JNED)
R246  ValueDisplayed: 80.6k  [0603L]  (hidden comment: CRCW060380K6FKEA)
R247  ValueDisplayed: 25.5k  [0603L]  (hidden comment: RC0603FR-0725K5L)
R248  ValueDisplayed: 43.2k  [0603L]  (hidden comment: RC0603FR-0743K2L)
R249  ValueDisplayed: 30.1k  [0603L]  (hidden comment: CRCW060330K1FKEA)
R250  value 1.00k  [0402L]  (hidden comment: CRCW04021K00FKED)
R256  value 1.00k  [0402L]  (hidden comment: CRCW04021K00FKED)
R257  ValueDisplayed: 274k  [0402L]  (hidden comment: CRCW0402274KFKED)
R258  ValueDisplayed: 100k  [0402L]  (hidden comment: CRCW0402100KFKED)
U20  TPS79301DBVR  [DBV0006A_N]
U21  LMR70503TM/NOPB  [YFX0008ADAC]
U22  TPS72301DBVR  [DBV0005A_N]
U42  TPS72301DBVR  [DBV0005A_N]
U43  TPS63060DSC  [DSC0010E]
U44  TPS73201DBVR  [DBV0005A_N]
U45  TPS79301DBVR  [DBV0006A_N]
U48  LMR70503TM/NOPB  [YFX0008ADAC]
VIO_3P75_U19  TESTPOINT  [TP_VIA_060RND040]  (value not drawn)  (no BOM)
VIO_3P75_U23  TESTPOINT  [TP_VIA_060RND040]  (value not drawn)  (no BOM)
VIO_5V_DRV  TESTPOINT  [TP_VIA_060RND040]  (value not drawn)  (no BOM)
VIO_5V_LMC  TESTPOINT  [TP_VIA_060RND040]  (value not drawn)  (no BOM)
VIO_5V_LMH  TESTPOINT  [TP_VIA_060RND040]  (value not drawn)  (no BOM)
VIO_5V_LOGIC  TESTPOINT  [TP_VIA_060RND040]  (value not drawn)  (no BOM)
VIO_-1P25_U19  TESTPOINT  [TP_VIA_060RND040]  (value not drawn)  (no BOM)
VIO_-1P25_U23  TESTPOINT  [TP_VIA_060RND040]  (value not drawn)  (no BOM)

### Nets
5P0_12P0V_INT: C382.1 C383.1 U43.2(VIN)
GND: C276.2 C277.2 C278.2 C280.2 C281.2 C282.2 C283.2 C284.1 C285.1 C287.2 C288.2 C289.2 C290.2 C297.2 C298.2 C299.2 C300.2 C356.2 C357.2 C358.2 C359.2 C382.2 C383.2 C384.2 C385.2 C386.1 C387.1 C388.1 C389.2 C390.2 C391.2 C392.2 C393.2 C394.1 C395.2 C396.2 C397.1 C398.2 C399.2 C400.1 C401.2 C402.2 C404.2 C405.2 C406.2 C407.2 C408.2 C410.2 C411.2 C415.2 C416.2 C418.1 C419.1 FL1.2 FL2.2 FL3.2 L37.2 L41.2 R172.1 R177.1 R232.1 R244.1 R247.1 R249.1 U20.2(GND) U21.C1(GND) U21.C2(GND) U22.1(GND) U42.1(GND) U43.4(PS/SYNC) U43.7(GND) U43.11(PGND) U44.2(GND) U45.2(GND) U48.C1(GND) U48.C2(GND)
VIO_1P9V: R170.1 R173.1 R242.1 R250.1 R256.1
VIO_3: C410.1 C411.1 L54.2
VIO_3P75_U19: C280.1 C281.1 L43.2 VIO_3P75_U19.1
VIO_3P75_U23: C297.1 C298.1 L45.2 VIO_3P75_U23.1
VIO_4P05V: L35.1 L36.1 L40.1 L53.1
VIO_5: C389.1 C390.1 L50.2 U44.1(IN) U44.3(EN)
VIO_5V_DRV: C401.1 C402.1 FL2.3 VIO_5V_DRV.1
VIO_5V_LMC: C395.1 C396.1 FL1.3 VIO_5V_LMC.1
VIO_5V_LMH: C391.1 C392.1 L51.2 VIO_5V_LMH.1
VIO_5V_LOGIC: C398.1 C399.1 FL3.3 VIO_5V_LOGIC.1
VIO_-1P25_U19: C289.1 C290.1 L44.2 VIO_-1P25_U19.1
VIO_-1P25_U23: C299.1 C300.1 L46.2 VIO_-1P25_U23.1
VIO_-3: C404.1 C405.1 L52.2
VIO_-3_LMH: C358.1 C359.1 L48.2
VIO_-3P25_1: C287.1 C288.1 L42.2 U22.2(IN) U22.3(EN)
VIO_-3P25_2: C356.1 C357.1 L47.2 U42.2(IN) U42.3(EN)
VIO_5V: C386.2 C387.2 C388.2 C394.2 C397.2 C400.2 C403.2 FL1.1 FL2.1 FL3.1 L50.1 R243.1 R245.2 U43.9(VOUT)
VIO_-3P25V_1: C284.2 C285.2 C286.1 D1.2(A) L42.1 R174.2 U21.B2(VOUT)
VIO_-3P25V_2: C417.1 C418.2 C419.2 D7.2(A) L47.1 R257.2 U48.B2(VOUT)
NetC276_1: C276.1 C277.1 L35.2 U20.1(IN)
NetC278_1: C278.1 U20.4(NR)
NetC279_1: C279.1 L43.1 L45.1 R171.1 U20.6(OUT)
NetC279_2: C279.2 R171.2 R172.2 U20.5(FB)
NetC282_1: C282.1 C283.1 L36.2 U21.D2(VIN)
NetC286_2: C286.2 R174.1 R175.2 U21.A2(FB)
NetC384_1: C384.1 U43.6(VAUX)
NetC385_1: C385.1 C403.1 R244.2 R245.1 U43.8(FB)
NetC393_1: C393.1 L51.1 R246.2 U44.5(OUT)
NetC406_1: C406.1 C407.1 L53.2 U45.1(IN)
NetC408_1: C408.1 U45.4(NR)
NetC409_1: C409.1 L54.1 R248.1 U45.6(OUT)
NetC409_2: C409.2 R248.2 R249.2 U45.5(FB)
NetC415_1: C415.1 C416.1 L40.2 U48.D2(VIN)
NetC417_2: C417.2 R257.1 R258.2 U48.A2(FB)
NetD1_1: D1.1(K) L37.1 U21.D1(SW)
NetD7_1: D7.1(K) L41.1 U48.D1(SW)
NetL44_1: L44.1 L46.1 R176.2 U22.5(OUT)
NetL48_1: L48.1 L52.1 R231.2 U42.5(OUT)
NetL49_1: L49.1 U43.1(L1)
NetL49_2: L49.2 U43.10(L2)
NetR170_2: R170.2 U20.3(EN)
NetR173_2: R173.2 U21.B1(EN)
NetR175_1: R175.1 U21.A1(VREF)
NetR176_1: R176.1 R177.2 U22.4(FB)
NetR231_1: R231.1 R232.2 U42.4(FB)
NetR242_2: R242.2 U43.3(EN)
NetR243_2: R243.2 U43.5(PG)
NetR246_1: R246.1 R247.2 U44.4(NR/FB)
NetR250_2: R250.2 U45.3(EN)
NetR256_2: R256.2 U48.B1(EN)
NetR258_1: R258.1 U48.A1(VREF)

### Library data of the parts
C276 C280 C282 C289 C297 C299 C358 C391 C395 C398 C401 C404 C406 C410 C415 = C1608X5R1A106M: as C150 on sheet TSW12J64EVM_B_8_Power
C277 C281 C283 C288 C290 C298 C300 C357 C359 C390 C392 C393 C396 C399 C402 C405 C407 C411 C416 = 06033C104JAT2A: as C116 on sheet TSW12J64EVM_B_8_Power
C278 C408 = 06031C103MAT2A: as C128 on sheet TSW12J64EVM_B_8_Power
C279 = C0603C150J5GACTU: CAP, CERM, 15 pF, 50 V, +/- 5%, C0G/NP0, 0603; Manufacturer: Kemet; Polarized: N; CompType: Capacitor; Value: 15pF; U/M: EA; Cap_F: 0.000000000015; Tolerance_%: 5; Value1: Unknown; VDC_V: 50; Value2: 50V; TaMin_C: -55; TaMax_C: 125; Cap_Case: 0603
C284 C285 C418 C419 = C1608X5R0J226M080AC: CAP, CERM, 22 µF, 6.3 V, +/- 20%, X5R, 0603; Manufacturer: TDK; Polarized: N; CompType: Capacitor; Value: 22uF; U/M: EA; Cap_F: 0.000022; Tolerance_%: 20; Value1: Unknown; VDC_V: 6.3; Value2: 6.3V; TaMin_C: -55; TaMax_C: 85; Cap_Case: 0603
C286 C385 C417 = GRM1555C1H100JA01D: CAP, CERM, 10 pF, 50 V, +/- 5%, C0G/NP0, 0402; Manufacturer: MuRata; Polarized: N; CompType: Capacitor; Value: 10pF; U/M: EA; Cap_F: 0.00000000001; Tolerance_%: 5; Value1: Unknown; VDC_V: 50; Value2: 50V; TaMin_C: -55; TaMax_C: 125; Cap_Case: 0402
C287 C356 C389 = GRM188R61A225KE34D: CAP, CERM, 2.2 µF, 10 V, +/- 10%, X5R, 0603; Manufacturer: MuRata; Polarized: N; CompType: Capacitor; Value: 2.2uF; U/M: EA; Cap_F: 0.0000022; Tolerance_%: 10; Value1: Unknown; Value2: 10V; TaMin_C: -55; TaMax_C: 85; Cap_Case: 0603
C382 C383 = EMK212BJ106KG-T: as C145 on sheet TSW12J64EVM_B_8_Power
C384 = C1005X5R1A104K: CAP, CERM, 0.1uF, 10V, +/-10%, X5R, 0402; Manufacturer: TDK; Polarized: N; CompType: Capacitor; U/M: EA; Cap_F: 0.0000001; Tolerance_%: 10; ESR_Ohm: 0.0186; Value1: 0.0186 ohm; TaMin_C: -55; TaMax_C: 85; Cap_Case: 0402
C386-C388 C394 C397 C400 = C2012X5R1C226K125AC: CAP, CERM, 22 µF, 16 V, +/- 10%, X5R, 0805; Manufacturer: TDK; Polarized: N; CompType: Capacitor; Value: 22uF; U/M: EA; Cap_F: 0.000022; Tolerance_%: 10; Value1: Unknown; VDC_V: 16; Value2: 16V; TaMin_C: -55; TaMax_C: 85; Cap_Case: 0805; AEC Category: Q200
C403 = Capacitor: CAP, CERM, xxxF, xxV, [TempCo], xx%, [PackageReference]; Polarized: N; U/M: EA
C409 = C0603C220J5GACTU: CAP, CERM, 22 pF, 50 V, +/- 5%, C0G/NP0, 0603; Manufacturer: Kemet; Polarized: N; CompType: Capacitor; Value: 22pF; U/M: EA; Cap_F: 0.000000000022; Tolerance_%: 5; Value1: Unknown; VDC_V: 50; Value2: 50V; TaMin_C: -55; TaMax_C: 125; Cap_Case: 0603; AEC Category: Q200
D1 D7 = PMEG3005EL,315: Diode, Schottky, 30 V, 0.5 A, SOD882; Manufacturer: NXP Semiconductor; U/M: EA; Vf_V: 0.5; Value: 30V; Value1: 0.5A; Value2: 0.5V; Vr_V: 30; TJmax_C: 150
FL1-FL3 = NFM41PC204F1H3L: Filter, LC, 0.2uF, 1806, SMT; Manufacturer: MuRata; SymbolCreator: a0799628
L35 L36 L40 L42-L48 L50-L54 = BLM18SG121TN1D: as L7 on sheet TSW12J64EVM_B_8_Power
L37 L41 = VLS2012ET-6R8M: Inductor, Shielded, Ferrite, 6.8 µH, 0.57 A, 0.498 ohm, SMD; Manufacturer: TDK; Value: 6.8uH; Ind_H: 6.8E-6; Imax_A: 0.57; Irms: 0.69A @ 40C rise; Isat: 0.57A @ 30% inductance drop; DCR_ohm: 0.498; Value2: 0.57A
L49 = XFL4020-102MEB: Inductor, Shielded, Composite, 1 µH, 5.4 A, 0.01 ohm, SMD; Manufacturer: Coilcraft; Value: 1uH; Ind_H: 1.0E-6; Imax_A: 5.4; Irms: 11A @ 40C rise; Isat: 5.4A @ 30% inductance drop; DCR_ohm: 0.01; Value2: 5.4A; AEC Category: Q200
R170 R173 R242 R250 R256 = CRCW04021K00FKED: RES, 1.00k ohm, 1%, 0.063W, 0402; Manufacturer: Vishay-Dale; CompType: Resistor; Res_ohm: 1000; Value_Code: 1k00; Tolerance_%: 1; Power_W: 0.063; VDC_V: 50; TempCo: 100 ppm/C; EIA_Code: E96; U/M: EA
R171 = RC0603FR-0762KL: RES, 62.0 k, 1%, 0.1 W, 0603; Manufacturer: Yageo America; CompType: Resistor; Value: 62.0k; Res_ohm: 62000; Value_Code: 62k0; Tolerance_%: 1; Power_W: 0.1; Value2: 0.1W; VDC_V: 150; TempCo: 200 ppm/C; U/M: EA
R172 R249 = CRCW060330K1FKEA: RES, 30.1 k, 1%, 0.1 W, 0603; Manufacturer: Vishay-Dale; CompType: Resistor; Value: 30.1k; Res_ohm: 30100; Value_Code: 30k1; Tolerance_%: 1; Power_W: 0.1; Value2: 0.1W; VDC_V: 75; TempCo: 100 ppm/C; EIA_Code: E96; U/M: EA
R174 R257 = CRCW0402274KFKED: RES, 274 k, 1%, 0.063 W, 0402; Manufacturer: Vishay-Dale; CompType: Resistor; Value: 274k; Res_ohm: 274000; Tolerance_%: 1; Power_W: 0.063; Value2: 0.063W; VDC_V: 50; TempCo: 100 ppm/C; EIA_Code: E96; U/M: EA
R175 R258 = CRCW0402100KFKED: RES, 100 k, 1%, 0.063 W, 0402; Manufacturer: Vishay-Dale; CompType: Resistor; Value: 100k; Res_ohm: 100000; Tolerance_%: 1; Power_W: 0.063; Value2: 0.063W; VDC_V: 50; TempCo: 100 ppm/C; EIA_Code: E96; U/M: EA
R176 = CRCW06035K23FKEA: RES, 5.23 k, 1%, 0.1 W, 0603; Manufacturer: Vishay-Dale; CompType: Resistor; Value: 5.23k; Res_ohm: 5230; Value_Code: 5k23; Tolerance_%: 1; Power_W: 0.1; Value2: 0.1W; VDC_V: 75; TempCo: 100 ppm/C; EIA_Code: E96; U/M: EA
R177 = RC0603FR-0795K3L: as R72 on sheet TSW12J64EVM_B_8_Power
R231 = CRCW060360K4FKEA: RES, 60.4 k, 1%, 0.1 W, 0603; Manufacturer: Vishay-Dale; CompType: Resistor; Value: 60.4k; Res_ohm: 60400; Value_Code: 60k4; Tolerance_%: 1; Power_W: 0.1; Value2: 0.1W; VDC_V: 75; TempCo: 100 ppm/C; EIA_Code: E96; U/M: EA; AEC Category: Q200
R232 = RC0603FR-0739K2L: RES, 39.2 k, 1%, 0.1 W, 0603; Manufacturer: Yageo America; CompType: Resistor; Value: 39.2k; Res_ohm: 39200; Value_Code: 39k2; Tolerance_%: 1; Power_W: 0.1; Value2: 0.1W; VDC_V: 150; TempCo: 200 ppm/C; EIA_Code: E96; U/M: EA; AEC Category: Q200
R243 R245 = CRCW04021M00JNED: RES, 1.0Meg ohm, 5%, 0.063W, 0402; Manufacturer: Vishay-Dale; CompType: Resistor; Res_ohm: 1000000; Value_Code: 1M00; Tolerance_%: 5; Power_W: 0.063; VDC_V: 50; TempCo: 200 ppm/C; EIA_Code: E24; U/M: EA
R244 = CRCW0402110KFKED: RES, 110 k, 1%, 0.063 W, 0402; Manufacturer: Vishay-Dale; CompType: Resistor; Value: 110k; Res_ohm: 110000; Tolerance_%: 1; Power_W: 0.063; Value2: 0.063W; VDC_V: 50; TempCo: 100 ppm/C; EIA_Code: E96; U/M: EA; AEC Category: Q200
R246 = CRCW060380K6FKEA: RES, 80.6 k, 1%, 0.1 W, 0603; Manufacturer: Vishay-Dale; CompType: Resistor; Value: 80.6k; Res_ohm: 80600; Value_Code: 80k6; Tolerance_%: 1; Power_W: 0.1; Value2: 0.1W; VDC_V: 75; TempCo: 100 ppm/C; EIA_Code: E96; U/M: EA; AEC Category: Q200
R247 = RC0603FR-0725K5L: RES, 25.5 k, 1%, 0.1 W, 0603; Manufacturer: Yageo America; CompType: Resistor; Value: 25.5k; Res_ohm: 25500; Value_Code: 25k5; Tolerance_%: 1; Power_W: 0.1; Value2: 0.1W; VDC_V: 150; TempCo: 200 ppm/C; EIA_Code: E96; U/M: EA; AEC Category: Q200
R248 = RC0603FR-0743K2L: RES, 43.2 k, 1%, 0.1 W, 0603; Manufacturer: Yageo America; CompType: Resistor; Value: 43.2k; Res_ohm: 43200; Value_Code: 43k2; Tolerance_%: 1; Power_W: 0.1; Value2: 0.1W; VDC_V: 150; TempCo: 200 ppm/C; EIA_Code: E96; U/M: EA; AEC Category: Q200
U20 U45 = TPS79301DBVR: Single Output High PSRR LDO, 200 mA, Adjustable 1.22 to 5.5 V Output, 2.7 to 5.5 V Input, 6-pin SOT-23 (DBV), -40 to 85 degC, Green (RoHS & no Sb/Br); Manufacturer: Texas Instruments; Alternate Manufacturer: None; Alternate PartNumber: Equivalent; Accuracy(%): 2; Iout(Max)(A): 0.2; Rating: Catalog; SubFamily: Single Channel LDO; Vdo(Typ)(mV): 77; Vin(Max)(V): 5.5; Vin(Min)(V): 2.7; Vout Adj(Min)(V): 1.22
U21 U48 = LMR70503TM/NOPB: SIMPLE SWITCHER Buck-Boost Converter For Negative Output Voltage in uSMD, YFX0008ADAC; Manufacturer: Texas Instruments; SymbolCreator: a0411947; CompType: IC; U/M: EA
U22 U42 = TPS72301DBVR: Single Output LDO, 200 mA, Adjustable -10 to -1.2 V Output, -10 to -2.7 V Input, 5-pin SOT-23 (DBV), -40 to 125 degC, Green (RoHS & no Sb/Br); Manufacturer: Texas Instruments; Alternate Manufacturer: None; Alternate PartNumber: Equivalent; Accuracy(%): 2; Iout(Max)(A): 0.2; Iq(Typ)(mA): 0.13; SubFamily: Single Channel LDO; Vdo(Typ)(mV): 280
U43 = TPS63060DSC: High Input Voltage Buck-Boost Converter with 2 A Switch Current, DSC0010E; Manufacturer: Texas Instruments; SymbolCreator: Altium; CompType: IC; U/M: EA
U44 = TPS73201DBVR: Cap-Free, NMOS, 250mA Low Dropout Regulator with Reverse Current Protection, DBV0005A; Alternate PartNumber: TPS73201DBVT; Manufacturer: Texas Instruments; SymbolCreator: a0411947; CompType: IC; U/M: EA
VIO_3P75_U19 VIO_3P75_U23 VIO_5V_DRV VIO_5V_LMC VIO_5V_LMH VIO_5V_LOGIC VIO_-1P25_U19 VIO_-1P25_U23 = TESTPOINT: TEST POINT.  No entry in BOM.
